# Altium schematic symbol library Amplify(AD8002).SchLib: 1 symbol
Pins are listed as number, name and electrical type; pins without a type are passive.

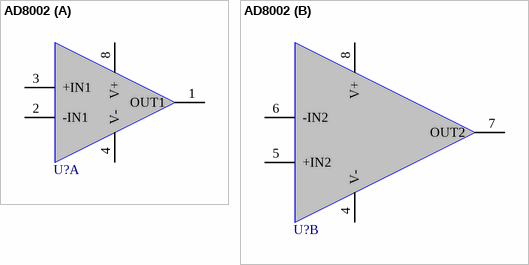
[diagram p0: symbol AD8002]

## AD8002
designator U?  (value not drawn)
Dual 600 MHz, 50 mW / Current Feedback Amplifier; Manufacturer: Analog Devices; Class 1: Amplify Devices
part A pins: 1 OUT1, 2 -IN1, 3 +IN1, 4 V- (power), 8 V+ (power)
part B pins: 4 V-, 5 +IN2, 6 -IN2, 7 OUT2, 8 V+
